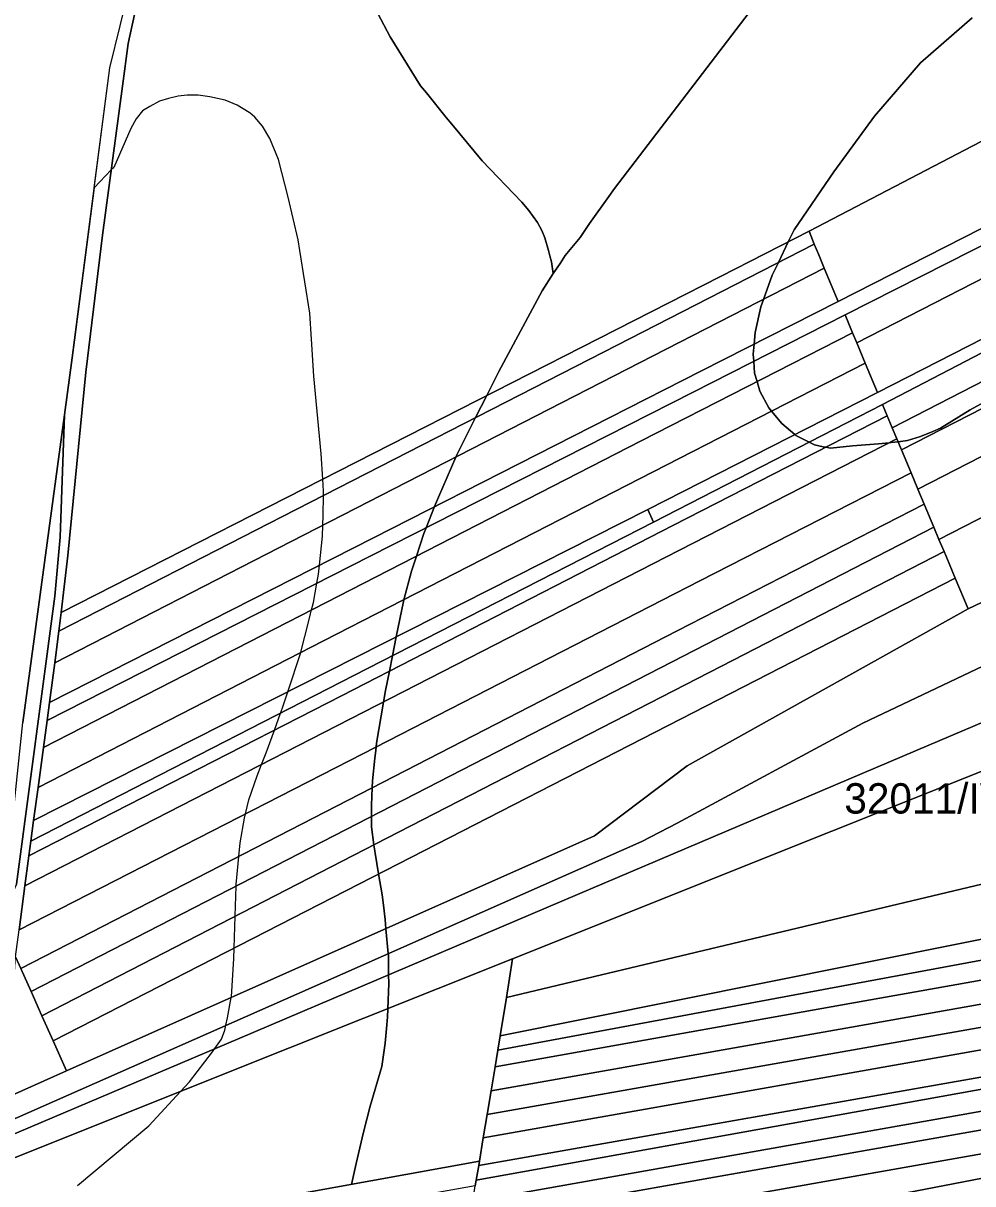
# Model space of a CAD drawing. Extents: x -521939 to -516426, y -1197857 to -1189551.
# Drawn here: x -521532 to -521063, y -1190786 to -1190213 of the extents above; entities that cross this region are included whole.
import ezdxf

# ---------------------------------------------------------------- set-up
doc = ezdxf.new("R2010")
doc.units = 0
for name, color, linetype in [('95560013', 7, 'Continuous'), ('95640013', 7, 'Continuous'), ('95660013', 7, 'Continuous')]:
    doc.layers.add(name, color=color, linetype=linetype)

msp = doc.modelspace()

# ---------------------------------------------------------------- linework, layer by layer
at = {"layer": '95560013'}
msp.add_lwpolyline([(-520777.95, -1190124.57), (-521143.74, -1190315.4), (-521187.47, -1190337.7), (-521350.33, -1190420.75), (-521513.19, -1190503.8), (-521509.92, -1190475.58), (-521501.05, -1190385.07), (-521492.81, -1190317.35), (-521482.93, -1190243.69), (-521480.04, -1190222.68), (-521467.81, -1190165.95)], dxfattribs=at)
for points in [[(-521143.74, -1190315.4), (-520777.95, -1190124.57), (-520777.29, -1190138.74), (-520776.47, -1190163.36), (-520776.83, -1190170.44), (-521129.32, -1190350.03), (-521136.18, -1190333.63), (-521138.91, -1190327.09), (-521141.12, -1190321.7)], [(-521125.92, -1190356.73), (-521201.05, -1190394.9), (-521360.62, -1190475.97), (-521520.19, -1190557.04), (-521519.05, -1190548.23), (-521358.95, -1190466.81), (-521197.1, -1190384.5), (-521129.32, -1190350.03), (-520776.83, -1190170.44), (-520777.49, -1190180.07), (-520800.29, -1190191.63), (-520962.75, -1190274)], [(-521125.92, -1190356.73), (-520962.75, -1190274), (-520800.29, -1190191.63), (-520777.49, -1190180.07), (-520778.53, -1190195.44), (-520799.56, -1190206.22), (-520959.86, -1190288.39), (-521120.16, -1190370.56), (-521122.27, -1190365.51)], [(-521120.16, -1190370.56), (-520959.86, -1190288.39), (-520799.56, -1190206.22), (-520778.53, -1190195.44), (-520780.79, -1190226.94), (-520945.61, -1190311.1), (-521109.96, -1190395.02), (-521115.96, -1190380.58)], [(-520780.79, -1190226.94), (-520781.3, -1190231.43), (-520947.47, -1190317.86), (-521107.43, -1190401.06), (-521220.55, -1190459.05), (-521223.37, -1190452.93), (-521109.96, -1190395.02), (-520945.61, -1190311.1)], [(-521107.43, -1190401.06), (-520947.47, -1190317.86), (-520781.3, -1190231.43), (-520784.36, -1190249.11), (-520942.18, -1190330.09), (-521102.67, -1190412.44), (-521105.13, -1190406.56)], [(-521102.67, -1190412.44), (-520942.18, -1190330.09), (-520784.36, -1190249.11), (-520786.83, -1190263.81), (-520937.98, -1190341.34), (-521098.02, -1190423.43), (-521100.33, -1190417.95)], [(-521098.02, -1190423.43), (-520937.98, -1190341.34), (-520786.83, -1190263.81), (-520791.44, -1190289.68), (-520928.2, -1190359.84), (-521089.93, -1190442.81), (-521093.32, -1190434.69)], [(-520799.14, -1190323.82), (-520918.15, -1190384.84), (-521079.58, -1190467.61), (-521082.1, -1190461.56), (-521086.88, -1190450.16), (-521089.93, -1190442.81), (-520928.2, -1190359.84), (-520791.44, -1190289.68)], [(-521403.81, -1190456.36), (-521514.36, -1190513.03), (-521513.19, -1190503.8), (-521350.33, -1190420.75), (-521187.47, -1190337.7), (-521143.74, -1190315.4), (-521141.12, -1190321.7), (-521245.33, -1190375.12)], [(-521136.18, -1190333.63), (-521240.35, -1190387.03), (-521399.59, -1190468.66), (-521516.42, -1190528.55), (-521514.36, -1190513.03), (-521403.81, -1190456.36), (-521245.33, -1190375.12), (-521141.12, -1190321.7), (-521138.91, -1190327.09)], [(-521079.58, -1190467.61), (-520918.15, -1190384.84), (-520799.14, -1190323.82), (-520803.11, -1190340.79), (-520817.75, -1190406.02), (-520856.45, -1190418.91), (-520952.31, -1190462.12), (-521016.12, -1190478.68), (-521065.06, -1190501.97), (-521071.49, -1190486.71), (-521074.5, -1190479.57), (-521077.03, -1190473.61)], [(-521136.18, -1190333.63), (-521129.32, -1190350.03), (-521197.1, -1190384.5), (-521358.95, -1190466.81), (-521519.05, -1190548.23), (-521516.42, -1190528.55), (-521399.59, -1190468.66), (-521240.35, -1190387.03)], [(-521520.19, -1190557.04), (-521360.62, -1190475.97), (-521201.05, -1190394.9), (-521125.92, -1190356.73), (-521122.27, -1190365.51), (-521226.65, -1190419.02), (-521388.75, -1190502.12), (-521522, -1190570.43)], [(-521388.75, -1190502.12), (-521226.65, -1190419.02), (-521122.27, -1190365.51), (-521120.16, -1190370.56), (-521115.96, -1190380.58), (-521220.66, -1190434.27), (-521383.59, -1190517.82), (-521524.62, -1190590.14), (-521522, -1190570.43)], [(-521115.96, -1190380.58), (-521109.96, -1190395.02), (-521223.37, -1190452.93), (-521367.44, -1190525.86), (-521526.8, -1190606.53), (-521524.62, -1190590.14), (-521383.59, -1190517.82), (-521220.66, -1190434.27)], [(-521105.13, -1190406.56), (-521210.63, -1190460.67), (-521374.74, -1190544.84), (-521529.12, -1190624.02), (-521528.16, -1190616.73), (-521368.6, -1190534.94), (-521220.55, -1190459.05), (-521107.43, -1190401.06)], [(-521532.09, -1190558.06), (-521511.54, -1190406.16), (-521513.68, -1190466.49), (-521516.42, -1190495.63), (-521535.27, -1190638.02), (-521537.81, -1190643.46), (-521540.43, -1190663.29), (-521539.95, -1190669.59), (-521541.74, -1190684.97), (-521545.22, -1190702.33), (-521545.21, -1190692.04), (-521545.2, -1190681.76), (-521542.35, -1190654.87), (-521541.77, -1190649.45)], [(-521529.12, -1190624.02), (-521374.74, -1190544.84), (-521210.63, -1190460.67), (-521105.13, -1190406.56), (-521102.67, -1190412.44), (-521100.33, -1190417.95), (-521207.7, -1190473), (-521370.19, -1190556.31), (-521531.1, -1190638.81)], [(-521531.1, -1190638.81), (-521370.19, -1190556.31), (-521207.7, -1190473), (-521100.33, -1190417.95), (-521098.02, -1190423.43), (-521093.32, -1190434.69), (-521197.66, -1190488.16), (-521364.19, -1190573.5), (-521533.94, -1190660.49)], [(-521093.32, -1190434.69), (-521089.93, -1190442.81), (-521086.88, -1190450.16), (-521208.86, -1190512.89), (-521371.15, -1190596.35), (-521533.09, -1190679.63), (-521535.7, -1190673.87), (-521533.94, -1190660.49), (-521364.19, -1190573.5), (-521197.66, -1190488.16)], [(-521086.88, -1190450.16), (-521082.1, -1190461.56), (-521205.95, -1190525.3), (-521366.99, -1190608.18), (-521528.03, -1190691.06), (-521533.09, -1190679.63), (-521371.15, -1190596.35), (-521208.86, -1190512.89)], [(-521526.8, -1190606.53), (-521367.44, -1190525.86), (-521223.37, -1190452.93), (-521220.55, -1190459.05), (-521368.6, -1190534.94), (-521528.16, -1190616.73)], [(-521528.03, -1190691.06), (-521366.99, -1190608.18), (-521205.95, -1190525.3), (-521082.1, -1190461.56), (-521079.58, -1190467.61), (-521077.03, -1190473.61), (-521181.27, -1190527.25), (-521352.34, -1190615.28), (-521522.75, -1190702.97)], [(-521522.75, -1190702.97), (-521352.34, -1190615.28), (-521181.27, -1190527.25), (-521077.03, -1190473.61), (-521074.5, -1190479.57), (-521071.49, -1190486.71), (-521200.84, -1190553.09), (-521359.4, -1190634.46), (-521517.2, -1190715.44)], [(-521517.2, -1190715.44), (-521359.4, -1190634.46), (-521200.84, -1190553.09), (-521071.49, -1190486.71), (-521065.06, -1190501.97), (-521203.97, -1190579.5), (-521249.64, -1190614.02), (-521346.43, -1190657.14), (-521510.56, -1190730.26)], [(-521579.75, -1190768.48), (-521547.67, -1190758.86), (-521384.14, -1190686.63), (-521226.27, -1190616.9), (-521208.81, -1190607.77), (-521117.2, -1190558.41), (-521028.03, -1190516.13), (-521001.35, -1190508.14), (-520988.56, -1190506.62), (-520973.08, -1190511.3), (-520963.57, -1190517.89), (-521091.14, -1190572.1), (-521258.08, -1190643.04), (-521425.02, -1190713.98), (-521591.96, -1190784.92)], [(-521591.96, -1190784.92), (-521425.02, -1190713.98), (-521258.08, -1190643.04), (-521091.14, -1190572.1), (-520963.57, -1190517.89), (-520948.08, -1190528.14), (-520935.85, -1190533.17), (-520975.03, -1190548.84), (-521132.5, -1190611.82), (-521290.17, -1190674.88), (-521437.14, -1190733.56), (-521603.17, -1190799.85)], [(-520873.05, -1190556.16), (-520842.97, -1190551.61), (-520846.95, -1190587.68), (-520947.61, -1190611.64), (-521120.53, -1190652.8), (-521293.24, -1190693.91), (-521290.17, -1190674.88), (-521132.5, -1190611.82), (-520975.03, -1190548.84), (-520935.85, -1190533.17), (-520927.18, -1190536.7), (-520901.63, -1190552.85), (-520888.76, -1190558.89), (-520880.26, -1190560.73), (-520874.86, -1190558.72)], [(-521296.33, -1190712.88), (-521293.24, -1190693.91), (-521120.53, -1190652.8), (-520947.61, -1190611.64), (-520846.95, -1190587.68), (-520849.58, -1190623.3), (-520946.68, -1190642.77), (-521121.53, -1190677.83)], [(-521297.51, -1190719.97), (-521296.33, -1190712.88), (-521121.53, -1190677.83), (-520946.68, -1190642.77), (-520849.58, -1190623.3), (-520850.63, -1190636.95), (-520939.5, -1190653.46), (-521119.77, -1190686.95)], [(-521298.87, -1190728.16), (-521297.51, -1190719.97), (-521119.77, -1190686.95), (-520939.5, -1190653.46), (-520850.63, -1190636.95), (-520851.64, -1190648.56), (-520948.39, -1190665.78), (-521123.63, -1190696.97)], [(-521300.83, -1190740.08), (-521298.87, -1190728.16), (-521123.63, -1190696.97), (-520948.39, -1190665.78), (-520851.64, -1190648.56), (-520852.28, -1190660.73), (-520950.13, -1190678.04), (-521125.48, -1190709.06)], [(-521302.74, -1190751.74), (-521300.83, -1190740.08), (-521125.48, -1190709.06), (-520950.13, -1190678.04), (-520852.28, -1190660.73), (-520852.56, -1190672.24), (-520946.39, -1190688.81), (-521124.48, -1190720.26)], [(-521304.64, -1190763.28), (-521302.74, -1190751.74), (-521124.48, -1190720.26), (-520946.39, -1190688.81), (-520852.56, -1190672.24), (-520852.94, -1190683.51), (-520953.28, -1190701.23), (-521131.31, -1190732.67)], [(-521290.17, -1190674.88), (-521293.24, -1190693.91), (-521296.33, -1190712.88), (-521297.51, -1190719.97), (-521298.87, -1190728.16), (-521300.83, -1190740.08), (-521302.74, -1190751.74), (-521304.64, -1190763.28), (-521306.54, -1190774.85), (-521450.36, -1190800.76), (-521627.54, -1190832.68), (-521603.17, -1190799.85), (-521437.14, -1190733.56)], [(-521306.54, -1190774.85), (-521304.64, -1190763.28), (-521131.31, -1190732.67), (-520953.28, -1190701.23), (-520852.94, -1190683.51), (-520853.37, -1190697.08), (-520944.6, -1190713.16), (-521121.67, -1190744.37), (-521306.91, -1190777.02)], [(-521308.13, -1190784.21), (-521129.72, -1190752.09), (-520951.31, -1190719.97), (-520853.44, -1190702.35), (-520853.63, -1190713.88), (-520965.54, -1190733.72), (-521143.84, -1190765.33), (-521309.9, -1190794.77), (-521308.62, -1190787.06)], [(-521306.91, -1190777.02), (-521121.67, -1190744.37), (-520944.6, -1190713.16), (-520853.37, -1190697.08), (-520853.44, -1190702.35), (-520951.31, -1190719.97), (-521129.72, -1190752.09), (-521308.13, -1190784.21)], [(-521310.55, -1190798.66), (-521309.9, -1190794.77), (-521143.84, -1190765.33), (-520965.54, -1190733.72), (-520853.63, -1190713.88), (-520853.79, -1190723.11), (-520956.84, -1190741.35), (-521130.85, -1190772.15), (-521311.47, -1190804.12)], [(-520853.79, -1190723.11), (-520853.87, -1190735.1), (-520958.48, -1190753.58), (-521136, -1190784.94), (-521313.52, -1190816.3), (-521311.47, -1190804.12), (-521130.85, -1190772.15), (-520956.84, -1190741.35)], [(-521313.52, -1190816.3), (-521136, -1190784.94), (-520958.48, -1190753.58), (-520853.87, -1190735.1), (-520853.81, -1190743.83), (-520959.05, -1190764.12), (-521138.15, -1190798.65), (-521317.25, -1190833.18), (-521501.29, -1190868.66), (-521677.29, -1190902.59), (-521660.16, -1190877.52), (-521482.65, -1190846.17)], [(-521681.39, -1190911.18), (-521677.29, -1190902.59), (-521501.29, -1190868.66), (-521317.25, -1190833.18), (-521138.15, -1190798.65), (-520959.05, -1190764.12), (-520853.81, -1190743.83), (-520853.6, -1190752.22), (-520963.96, -1190774.66), (-521145.09, -1190811.49), (-521320.22, -1190847.1), (-521372.85, -1190856.47), (-521425.01, -1190865.8), (-521453.93, -1190870.89), (-521460.01, -1190871.96), (-521483.31, -1190876.02), (-521504.24, -1190879.82), (-521526.13, -1190883.61), (-521548.65, -1190887.54)], [(-521636.8, -1190845.39), (-521627.54, -1190832.68), (-521450.36, -1190800.76), (-521306.54, -1190774.85), (-521306.91, -1190777.02), (-521308.13, -1190784.21), (-521308.62, -1190787.06), (-521459.01, -1190813.79)]]:
    msp.add_lwpolyline(points, close=True, dxfattribs=at)
at = {"layer": '95640013'}
for points in [[(-521535.27, -1190638.02), (-521516.42, -1190495.63), (-521513.68, -1190466.49), (-521511.54, -1190406.16), (-521507.71, -1190377.86), (-521489.18, -1190234.62), (-521463.67, -1190130.83)], [(-521467.81, -1190165.95), (-521480.04, -1190222.68), (-521482.93, -1190243.69), (-521492.81, -1190317.35), (-521501.05, -1190385.07), (-521509.92, -1190475.58), (-521513.19, -1190503.8), (-521514.36, -1190513.03), (-521516.42, -1190528.55), (-521519.05, -1190548.23), (-521520.19, -1190557.04), (-521522, -1190570.43), (-521524.62, -1190590.14), (-521526.8, -1190606.53), (-521528.16, -1190616.73), (-521529.12, -1190624.02), (-521531.1, -1190638.81), (-521533.94, -1190660.49)]]:
    msp.add_lwpolyline(points, dxfattribs=at)
for points in [[(-521510.56, -1190730.26), (-521346.43, -1190657.14), (-521249.64, -1190614.02), (-521203.97, -1190579.5), (-521065.06, -1190501.97), (-521016.12, -1190478.68), (-520952.31, -1190462.12), (-520856.45, -1190418.91), (-520817.75, -1190406.02), (-520822, -1190424.77), (-520866.64, -1190438.5), (-520903.05, -1190454.36), (-520931.67, -1190464.89), (-520954.38, -1190471.58), (-520975.71, -1190484.83), (-521028.03, -1190516.13), (-521117.2, -1190558.41), (-521208.81, -1190607.77), (-521226.27, -1190616.9), (-521384.14, -1190686.63), (-521547.67, -1190758.86), (-521579.75, -1190768.48), (-521566.68, -1190750.61), (-521543.77, -1190745.06)], [(-521545.25, -1190723.06), (-521538.23, -1190695.26), (-521536.66, -1190686.14), (-521535.7, -1190673.87), (-521533.09, -1190679.63), (-521528.03, -1190691.06), (-521522.75, -1190702.97), (-521517.2, -1190715.44), (-521510.56, -1190730.26), (-521543.77, -1190745.06), (-521566.68, -1190750.61)]]:
    msp.add_lwpolyline(points, close=True, dxfattribs=at)
at = {"layer": '95660013'}
for points in [[(-521505.15, -1190786.81), (-521469.92, -1190757.37), (-521454.19, -1190740.37), (-521449.75, -1190735.57), (-521438.39, -1190720.74), (-521437.31, -1190719.2), (-521433.98, -1190714.48), (-521432.36, -1190710.07), (-521431.81, -1190707.69), (-521430.97, -1190704.05), (-521429.19, -1190694.01), (-521429.12, -1190693.61), (-521427.96, -1190674.61), (-521427.8, -1190669.56), (-521427.3, -1190653.85), (-521426.82, -1190638.97), (-521426.8, -1190638.21), (-521425.38, -1190624.24), (-521424.71, -1190617.58), (-521422.63, -1190605.29), (-521422.15, -1190603.2), (-521420.54, -1190596.25), (-521416.37, -1190584.43), (-521414.22, -1190578.88), (-521411.96, -1190573.07), (-521407.87, -1190561.83), (-521404.84, -1190553.51), (-521403.85, -1190550.81), (-521401.26, -1190542.98), (-521394.85, -1190523.59), (-521394.57, -1190522.76), (-521390.96, -1190508.46), (-521389.96, -1190504.46), (-521389.46, -1190502.48), (-521388.55, -1190498.88), (-521386.82, -1190489.28), (-521386, -1190484.74), (-521385.56, -1190480.34), (-521384.14, -1190465.97), (-521383.93, -1190460.63), (-521383.74, -1190455.75), (-521383.64, -1190446.02), (-521383.62, -1190443.74), (-521383.99, -1190437.92), (-521384.79, -1190425.42), (-521388.4, -1190386.93), (-521389.56, -1190368.78), (-521390.39, -1190355.79), (-521395.26, -1190324.96), (-521396.1, -1190319.63), (-521401.12, -1190298.64), (-521405.9, -1190279.97), (-521410.1, -1190269.59), (-521413.71, -1190263.41), (-521417.56, -1190259.09), (-521420.07, -1190256.92), (-521420.25, -1190256.76), (-521426.31, -1190253.15), (-521432.14, -1190250.7), (-521439.73, -1190248.95), (-521445.56, -1190248.25), (-521451.04, -1190248.13), (-521455.47, -1190248.6), (-521460.14, -1190249.88), (-521464.57, -1190251.16), (-521469.35, -1190253.73), (-521472.97, -1190255.95), (-521476.15, -1190259.94), (-521478.81, -1190264.69), (-521487.27, -1190283.83), (-521488.48, -1190285.1), (-521496.84, -1190293.87), (-521496.85, -1190293.88), (-521489.18, -1190234.62), (-521463.67, -1190130.83)], [(-521369.85, -1190786.26), (-521367.46, -1190775.97), (-521363.86, -1190760.5), (-521360.5, -1190747.63), (-521354.82, -1190728.04), (-521353.19, -1190716.45), (-521352.54, -1190709.24), (-521352.04, -1190703.7), (-521351.86, -1190699.51), (-521351.34, -1190687.01), (-521351.41, -1190682.7), (-521351.57, -1190673.1), (-521351.65, -1190672.28), (-521352.78, -1190659.97), (-521353.19, -1190655.48), (-521354.01, -1190648.29), (-521354.59, -1190643.19), (-521356.36, -1190632.9), (-521358.12, -1190622.66), (-521358.29, -1190621.63), (-521358.71, -1190618.56), (-521359.92, -1190609.58), (-521359.92, -1190604.54), (-521359.92, -1190598.92), (-521359.59, -1190590.4), (-521359.45, -1190586.86), (-521358.2, -1190575.68), (-521357.78, -1190572.01), (-521357.57, -1190570.11), (-521357.37, -1190568.31), (-521353.91, -1190547.97), (-521352.96, -1190542.35), (-521351.03, -1190532.68), (-521349.53, -1190525.16), (-521347.67, -1190515.85), (-521344.15, -1190498.3), (-521343.93, -1190497.48), (-521340.11, -1190483.39), (-521337.69, -1190475.95), (-521334.05, -1190464.73), (-521332.91, -1190461.89), (-521328.69, -1190451.42), (-521326.82, -1190446.77), (-521318.27, -1190426.97), (-521317.95, -1190426.24), (-521308.47, -1190407.49), (-521302.96, -1190396.6), (-521296.96, -1190384.72), (-521275.5, -1190344.83), (-521270.13, -1190336.24), (-521266.76, -1190331.3), (-521264.13, -1190327.45), (-521256.78, -1190318.41), (-521254.5, -1190315.09), (-521252.14, -1190311.65), (-521242.69, -1190298.29), (-521239.8, -1190294.2), (-521163.05, -1190193.89)], [(-521163.05, -1190193.89), (-521239.8, -1190294.2), (-521242.69, -1190298.29), (-521252.14, -1190311.65), (-521254.5, -1190315.09), (-521256.78, -1190318.41), (-521264.13, -1190327.45), (-521266.76, -1190331.3), (-521270.13, -1190336.24), (-521270.89, -1190330.58), (-521271.74, -1190327.62), (-521272.41, -1190324.92), (-521274.19, -1190318.58), (-521275.71, -1190315.03), (-521277.9, -1190311.15), (-521282.13, -1190305.23), (-521285.59, -1190301.09), (-521305.19, -1190280.65), (-521320.23, -1190262.57), (-521322.98, -1190259.15), (-521332.71, -1190247.07), (-521335.6, -1190243.48), (-521350.73, -1190219.4), (-521356.72, -1190207.83)], [(-521356.72, -1190207.83), (-521350.73, -1190219.4), (-521335.6, -1190243.48), (-521332.71, -1190247.07), (-521322.98, -1190259.15), (-521320.23, -1190262.57), (-521305.19, -1190280.65), (-521285.59, -1190301.09), (-521282.13, -1190305.23), (-521277.9, -1190311.15), (-521275.71, -1190315.03), (-521274.19, -1190318.58), (-521272.41, -1190324.92), (-521271.74, -1190327.62), (-521270.89, -1190330.58), (-521270.13, -1190336.24), (-521275.5, -1190344.83), (-521296.96, -1190384.72), (-521302.96, -1190396.6), (-521308.47, -1190407.49), (-521317.95, -1190426.24), (-521318.27, -1190426.97), (-521326.82, -1190446.77), (-521328.69, -1190451.42), (-521332.91, -1190461.89), (-521334.05, -1190464.73), (-521337.69, -1190475.95), (-521340.11, -1190483.39), (-521343.93, -1190497.48), (-521344.15, -1190498.3), (-521347.67, -1190515.85), (-521349.53, -1190525.16), (-521351.03, -1190532.68), (-521352.96, -1190542.35), (-521353.91, -1190547.97), (-521357.37, -1190568.31), (-521357.57, -1190570.11), (-521357.78, -1190572.01), (-521358.2, -1190575.68), (-521359.45, -1190586.86), (-521359.59, -1190590.4), (-521359.92, -1190598.92), (-521359.92, -1190604.54), (-521359.92, -1190609.58), (-521358.71, -1190618.56), (-521358.29, -1190621.63), (-521358.12, -1190622.66), (-521356.36, -1190632.9), (-521354.59, -1190643.19), (-521354.01, -1190648.29), (-521353.19, -1190655.48), (-521352.78, -1190659.97), (-521351.65, -1190672.28), (-521351.57, -1190673.1), (-521351.41, -1190682.7), (-521351.34, -1190687.01), (-521351.86, -1190699.51), (-521352.04, -1190703.7), (-521352.54, -1190709.24), (-521353.19, -1190716.45), (-521354.82, -1190728.04), (-521360.5, -1190747.63), (-521363.86, -1190760.5), (-521367.46, -1190775.97), (-521369.85, -1190786.26)], [(-521063.1, -1190209.93), (-521088.69, -1190232.24), (-521111.46, -1190258.53), (-521131.41, -1190285.99), (-521151.13, -1190314.63), (-521154.01, -1190320.64), (-521158.88, -1190330.8), (-521161.93, -1190337.17), (-521166.25, -1190349.04), (-521167.56, -1190352.66), (-521170.38, -1190365.34), (-521170.89, -1190371.17), (-521171.32, -1190376.14), (-521171.05, -1190379.66), (-521170.61, -1190385.53), (-521169.41, -1190389.68), (-521168.03, -1190394.45), (-521163.57, -1190402.66), (-521162.22, -1190404.3), (-521157.23, -1190410.41), (-521150.72, -1190415.83), (-521150.19, -1190416.28), (-521143.65, -1190419.63), (-521141.03, -1190420.97), (-521136.8, -1190421.85), (-521135.47, -1190422.12), (-521133.05, -1190422.62), (-521122.25, -1190421.44), (-521109.34, -1190420.5), (-521104.17, -1190419.92), (-521103.12, -1190419.8), (-521099.74, -1190419.36), (-521095.02, -1190418.74), (-521088.69, -1190416.86), (-521082.59, -1190414.35), (-521078.71, -1190412.76), (-521064.04, -1190403.6), (-521001.12, -1190369.09)], [(-521001.12, -1190369.09), (-521064.04, -1190403.6), (-521078.71, -1190412.76), (-521082.59, -1190414.35), (-521088.69, -1190416.86), (-521095.02, -1190418.74), (-521099.74, -1190419.36), (-521103.12, -1190419.8), (-521104.17, -1190419.92), (-521109.34, -1190420.5), (-521122.25, -1190421.44), (-521133.05, -1190422.62), (-521135.47, -1190422.12), (-521136.8, -1190421.85), (-521141.03, -1190420.97), (-521143.65, -1190419.63), (-521150.19, -1190416.28), (-521150.72, -1190415.83), (-521157.23, -1190410.41), (-521162.22, -1190404.3), (-521163.57, -1190402.66), (-521168.03, -1190394.45), (-521169.41, -1190389.68), (-521170.61, -1190385.53), (-521171.05, -1190379.66), (-521171.32, -1190376.14), (-521170.89, -1190371.17), (-521170.38, -1190365.34), (-521167.56, -1190352.66), (-521166.25, -1190349.04), (-521161.93, -1190337.17), (-521158.88, -1190330.8), (-521154.01, -1190320.64), (-521151.13, -1190314.63), (-521131.41, -1190285.99), (-521111.46, -1190258.53), (-521088.69, -1190232.24), (-521063.1, -1190209.93)], [(-521505.15, -1190786.81), (-521469.92, -1190757.37), (-521454.19, -1190740.37), (-521449.75, -1190735.57), (-521438.39, -1190720.74), (-521437.31, -1190719.2), (-521433.98, -1190714.48), (-521432.36, -1190710.07), (-521431.81, -1190707.69), (-521430.97, -1190704.05), (-521429.19, -1190694.01), (-521429.12, -1190693.61), (-521427.96, -1190674.61), (-521427.8, -1190669.56), (-521427.3, -1190653.85), (-521426.82, -1190638.97), (-521426.8, -1190638.21), (-521425.38, -1190624.24), (-521424.71, -1190617.58), (-521422.63, -1190605.29), (-521422.15, -1190603.2), (-521420.54, -1190596.25), (-521416.37, -1190584.43), (-521414.22, -1190578.88), (-521411.96, -1190573.07), (-521407.87, -1190561.83), (-521404.84, -1190553.51), (-521403.85, -1190550.81), (-521401.26, -1190542.98), (-521394.85, -1190523.59), (-521394.57, -1190522.76), (-521390.96, -1190508.46), (-521389.96, -1190504.46), (-521389.46, -1190502.48), (-521388.55, -1190498.88), (-521386.82, -1190489.28), (-521386, -1190484.74), (-521385.56, -1190480.34), (-521384.14, -1190465.97), (-521383.93, -1190460.63), (-521383.74, -1190455.75), (-521383.64, -1190446.02), (-521383.62, -1190443.74), (-521383.99, -1190437.92), (-521384.79, -1190425.42), (-521388.4, -1190386.93), (-521389.56, -1190368.78), (-521390.39, -1190355.79), (-521395.26, -1190324.96), (-521396.1, -1190319.63), (-521401.12, -1190298.64), (-521405.9, -1190279.97), (-521410.1, -1190269.59), (-521413.71, -1190263.41), (-521417.56, -1190259.09), (-521420.07, -1190256.92), (-521420.25, -1190256.76), (-521426.31, -1190253.15), (-521432.14, -1190250.7), (-521439.73, -1190248.95), (-521445.56, -1190248.25), (-521451.04, -1190248.13), (-521455.47, -1190248.6), (-521460.14, -1190249.88), (-521464.57, -1190251.16), (-521469.35, -1190253.73), (-521472.97, -1190255.95), (-521476.15, -1190259.94), (-521478.81, -1190264.69), (-521487.27, -1190283.83), (-521488.48, -1190285.1), (-521496.84, -1190293.87), (-521496.85, -1190293.88), (-521507.71, -1190377.86), (-521511.54, -1190406.16), (-521532.09, -1190558.06)]]:
    msp.add_lwpolyline(points, dxfattribs=at)

# ---------------------------------------------------------------- texts
msp.add_text('32011/IV.', height=15, rotation=0, dxfattribs=at).set_placement((-521126.31, -1190603.09))

doc.saveas('drawing.dxf')
